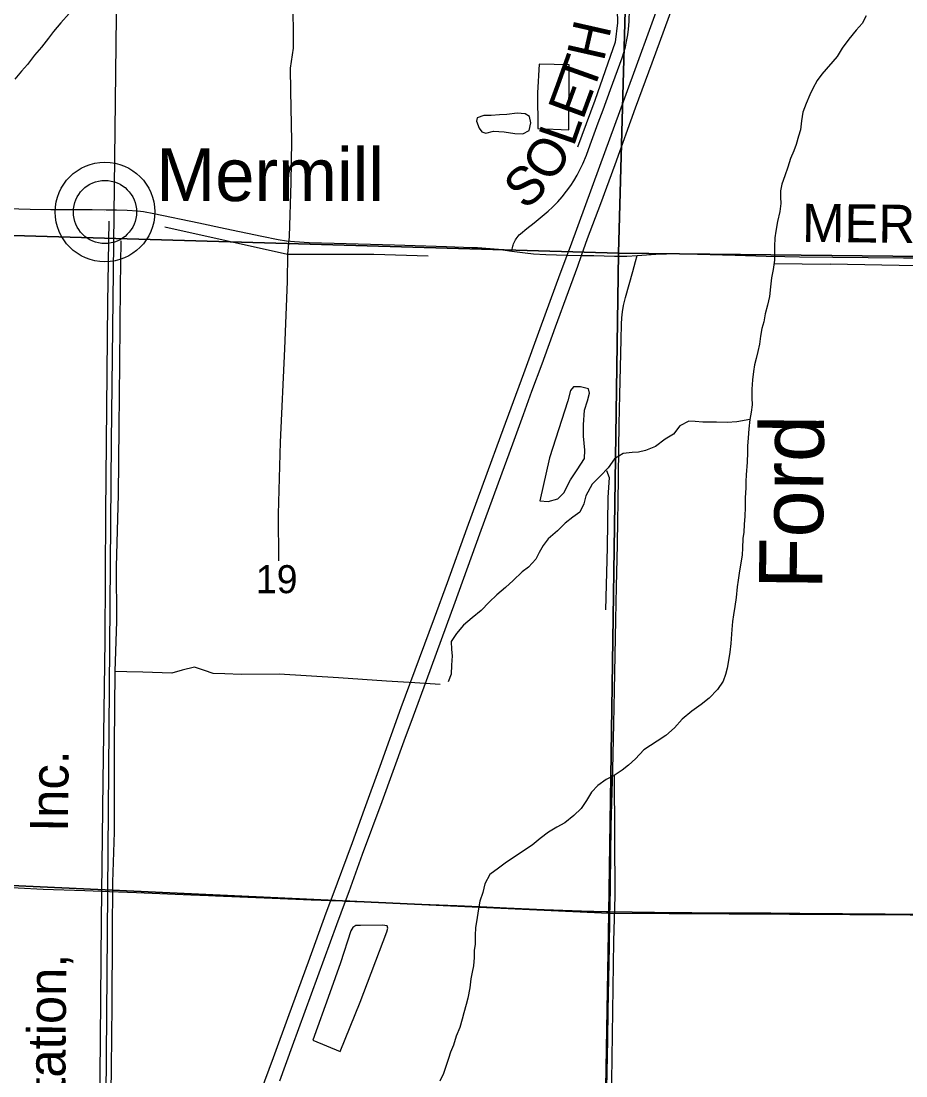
# Model space of a CAD drawing. Extents: x 1443599 to 1910620, y 1028088 to 1361369.
# Drawn here: x 1652830 to 1659809, y 1196448 to 1204767 of the extents above; entities that cross this region are included whole.
import ezdxf

# ---------------------------------------------------------------- set-up
doc = ezdxf.new("R2010")
doc.units = 0
for name, color, linetype in [('GM_X_County_Road', 7, 'Continuous'), ('GM_X_County_Road_Text', 7, 'Continuous'), ('GM_X_Interstate_Route', 7, 'Continuous'), ('GM_X_Major_River', 7, 'Continuous'), ('GM_X_Minor_Lake', 7, 'Continuous'), ('GM_X_Minor_River', 7, 'Continuous'), ('GM_X_Minor_River_Text', 7, 'Continuous'), ('GM_X_Rail_Line', 7, 'Continuous'), ('GM_X_Rail_Line_Text', 7, 'Continuous'), ('GM_X_Section', 7, 'Continuous'), ('GM_X_Section_Text', 7, 'Continuous'), ('GM_X_State_Route', 7, 'Continuous'), ('GM_X_Township_Road', 7, 'Continuous'), ('GM_X_Township_Road_Text', 7, 'Continuous'), ('GM_X_Unincorporated', 7, 'Continuous'), ('GM_X_Unincorporated_Location', 7, 'Continuous'), ('GM_X_Unincorporated_Text', 7, 'Continuous')]:
    doc.layers.add(name, color=color, linetype=linetype)

msp = doc.modelspace()

# ---------------------------------------------------------------- linework, layer by layer
at = {"layer": 'GM_X_County_Road'}
for points in [[(1652723.3, 1203288.1), (1652902, 1203285.3), (1653063.3, 1203281.9), (1653225.3, 1203281.7), (1653356.5, 1203281.9), (1653389.3, 1203281.1), (1653501.9, 1203279.5), (1653518.4, 1203279.8), (1653583.4, 1203278.8), (1653665.5, 1203276), (1653747.6, 1203270.4), (1653796.7, 1203264.5), (1653877.8, 1203250.5), (1654231.4, 1203176.9), (1654440.1, 1203132.7), (1654729.3, 1203072.1), (1654857.7, 1203045.3), (1654922.3, 1203034.8), (1654987.3, 1203028.2), (1655101.8, 1203022), (1655298.6, 1203017), (1655774.5, 1203003.8), (1656184.6, 1202990.6), (1656385.4, 1202982.4)], [(1656385.4, 1202982.4), (1656430.7, 1202980.5), (1656529.2, 1202974.1), (1656594.6, 1202967.2), (1656700.6, 1202952.9)], [(1656700.6, 1202952.9), (1656805.8, 1202938.7), (1656870.9, 1202932.6), (1656969, 1202927.5), (1657138.1, 1202922.4), (1657251.5, 1202919.7), (1657346.3, 1202917.5), (1657510.3, 1202913.7), (1657608.5, 1202914.1), (1657689.5, 1202917.9)], [(1657689.5, 1202917.9), (1657690.2, 1202918), (1657837.4, 1202928.9), (1657919.6, 1202932.4), (1658018.2, 1202933.2), (1658148.9, 1202930.5)], [(1658148.9, 1202930.5), (1658166, 1202930.1), (1658461.2, 1202920.3), (1658707.3, 1202913.5), (1658855, 1202910.7), (1658969.8, 1202908.8), (1659232.4, 1202905.8), (1659511.4, 1202903.2), (1659790.3, 1202899.4), (1660003.8, 1202898.9), (1660463.3, 1202894.1), (1660726, 1202891.3), (1660873.6, 1202889.6), (1661201.9, 1202888.9), (1661382.5, 1202888.2), (1661809.2, 1202883.8), (1662104.6, 1202881.3), (1662744.8, 1202877.5), (1662843, 1202876.5)]]:
    msp.add_lwpolyline(points, dxfattribs=at)
at = {"layer": 'GM_X_Interstate_Route'}
for points in [[(1654870, 1196408.2), (1654971.3, 1196685.7), (1655321.2, 1197641.2), (1655389.1, 1197827.1), (1655416.9, 1197903.3), (1655522.8, 1198196.6), (1655677.9, 1198611.7), (1655852.6, 1199089.6), (1655924.9, 1199288.3), (1656026.6, 1199567.6), (1656185.2, 1199999), (1656252.6, 1200184), (1656449.2, 1200723.7), (1656594.7, 1201124.9), (1656708.1, 1201432.9), (1656791.6, 1201664.5), (1656859.5, 1201849.4), (1656939.9, 1202064.7), (1657046.2, 1202356.3), (1657147.9, 1202635.2), (1657221.4, 1202835.5), (1657251.5, 1202919.7), (1657298.7, 1203051.8), (1657401.6, 1203328.8), (1657514.7, 1203636.9), (1657677.1, 1204084.3), (1657806.9, 1204438.7), (1658127.8, 1205317.5)], [(1654718.1, 1196316.8), (1654820, 1196594.1), (1654944.2, 1196933.2), (1655097.4, 1197349), (1655236.4, 1197735.1), (1655272.8, 1197831.8), (1655282.6, 1197857.9), (1655442.9, 1198288.7), (1655537.4, 1198551.2), (1655662.6, 1198889.9), (1655828.8, 1199353.4), (1655897, 1199538.1), (1656091.7, 1200061.2), (1656192.1, 1200339.1), (1656349.5, 1200770.8), (1656506.6, 1201202.7), (1656614.6, 1201495.3), (1656794.6, 1201988.7), (1656925, 1202343), (1657082.5, 1202774.7), (1657111.1, 1202851.5), (1657138.1, 1202922.4), (1657163.5, 1202989.6), (1657394, 1203621.9), (1657590.7, 1204161.6), (1657888.7, 1204978.9)]]:
    msp.add_lwpolyline(points, dxfattribs=at)
at = {"layer": 'GM_X_Major_River'}
for points in [[(1653208.1, 1204826.6), (1653143.8, 1204754.6), (1653085.5, 1204684.5), (1653045.3, 1204632.5), (1652990.9, 1204560.5), (1652936.7, 1204498.5), (1652880.3, 1204424.4)], [(1652880.3, 1204424.4), (1652832.1, 1204372.4), (1652781.8, 1204310.4)]]:
    msp.add_lwpolyline(points, dxfattribs=at)
at = {"layer": 'GM_X_Minor_Lake'}
for p, q in [((1656915, 1204426.7), (1656904.2, 1204202.1)), ((1656661.3, 1204030.3), (1656603.2, 1204028.5)), ((1656997.5, 1201321.6), (1656920.4, 1200984.9)), ((1655348.8, 1197338.8), (1655265.9, 1197104.3))]:
    msp.add_line(p, q, dxfattribs=at)
for points in [[(1656904.2, 1204202.1), (1656905.4, 1203919.3), (1657149.7, 1203910.6), (1657153.3, 1204422), (1656915, 1204426.7)], [(1656603.2, 1204028.5), (1656537.1, 1204022.7), (1656481, 1204022.8), (1656426.8, 1204004.9), (1656420.7, 1203976.9), (1656442.6, 1203922.7), (1656464.6, 1203894.5), (1656494.6, 1203884.4), (1656556.7, 1203898.3), (1656640.8, 1203894), (1656724.9, 1203881.8), (1656787, 1203877.6), (1656837.2, 1203903.5), (1656851.4, 1203965.6), (1656839.5, 1204013.8), (1656805.6, 1204035.9), (1656743.5, 1204042.1), (1656661.3, 1204030.3)], [(1656920.4, 1200984.9), (1656988.5, 1200978.7), (1657064.7, 1201000.5), (1657110.9, 1201046.5), (1657163.3, 1201148.7), (1657215.6, 1201228.8), (1657274, 1201316.8), (1657276.2, 1201383), (1657266.5, 1201493.4), (1657264.8, 1201583.6), (1657275.1, 1201699.9), (1657297.4, 1201772.1), (1657313.6, 1201832.2), (1657305.7, 1201866.3), (1657241.6, 1201882.6), (1657187.5, 1201882.7), (1657163.4, 1201852.7), (1657141.1, 1201772.5), (1656997.5, 1201321.6)], [(1655265.9, 1197104.3), (1655130.6, 1196729.6), (1655346.7, 1196640.8), (1655504.1, 1197029.4), (1655714.1, 1197584.5), (1655722.2, 1197614.5), (1655718.2, 1197630.6), (1655680.2, 1197636.7), (1655507.9, 1197635.2), (1655469.9, 1197635.3), (1655447.8, 1197619.3), (1655431.7, 1197593.3), (1655348.8, 1197338.8)]]:
    msp.add_lwpolyline(points, dxfattribs=at)
at = {"layer": 'GM_X_Minor_River'}
for points in [[(1655072, 1208204.2), (1656079.6, 1208169.2), (1657153.2, 1208123.9), (1657650, 1208106.4), (1657618.1, 1207553.1), (1657619.4, 1207342.5), (1657606.7, 1207138), (1657597.8, 1206853.3), (1657593.3, 1206694.9), (1657584.1, 1206317.9), (1657560.2, 1205748.5), (1657562.8, 1205299.2), (1657553.8, 1205000.4), (1657529.7, 1204962.4), (1657535, 1204753.8), (1657516.5, 1204601.4), (1657435.7, 1204375.1), (1657354.8, 1204140.6), (1657288.1, 1203958.3), (1657219.4, 1203772)], [(1654978, 1205694.1), (1654970.7, 1205350.9), (1654973.5, 1204971.9), (1654976.2, 1204554.7), (1654951.6, 1204396.3), (1654955.1, 1204213.8), (1654963.9, 1203822.7), (1654958.8, 1203493.8), (1654945.5, 1203068.6), (1654931, 1202928.2), (1654928.4, 1202713.6), (1654906.7, 1202182.2), (1654872.4, 1201446.2), (1654856.6, 1200878.6), (1654861.5, 1200509.5)], [(1659494.4, 1204810.1), (1659463.2, 1204748.5), (1659416.1, 1204695.2), (1659358.6, 1204624.1), (1659307.1, 1204554.9), (1659265.8, 1204487.4)], [(1659265.8, 1204487.4), (1659146.4, 1204350), (1659110.2, 1204298), (1659073.9, 1204235.9), (1659051.7, 1204185.8), (1659021.5, 1204117.7), (1658997.2, 1204049.6), (1658985, 1203979.4), (1658976.7, 1203909.3), (1658962.6, 1203859.2), (1658944.3, 1203795.1), (1658924.1, 1203743), (1658899.9, 1203682.9), (1658877.7, 1203614.7), (1658853.4, 1203546.6), (1658831.2, 1203480.5), (1658819, 1203428.4), (1658818.8, 1203378.2), (1658822.7, 1203328.1), (1658814.5, 1203265.9), (1658796.2, 1203185.8), (1658784, 1203111.6), (1658775.8, 1203057.5), (1658771.6, 1202989.3), (1658771.2, 1202883), (1658763, 1202808.8), (1658748.8, 1202742.6), (1658740.5, 1202670.5), (1658734.3, 1202596.3), (1658716, 1202528.1), (1658697.8, 1202458), (1658687.6, 1202395.8), (1658671.4, 1202343.7), (1658663.2, 1202283.6), (1658653, 1202219.4), (1658640.8, 1202161.3), (1658626.6, 1202107.2), (1658614.4, 1202057.1), (1658606.3, 1202004.9), (1658600, 1201936.8), (1658593.8, 1201864.6), (1658593.6, 1201796.4), (1658595.4, 1201740.2), (1658587.2, 1201684.1), (1658579, 1201623.9), (1658570.8, 1201551.8), (1658564.6, 1201479.6), (1658560.4, 1201415.4), (1658560.2, 1201365.2), (1658556, 1201289), (1658547.7, 1201188.8), (1658545.5, 1201136.6), (1658545.3, 1201086.5), (1658541.1, 1201008.3), (1658540.9, 1200932.1), (1658538.7, 1200861.8), (1658534.5, 1200797.7), (1658530.3, 1200735.5), (1658522.1, 1200685.4), (1658519.8, 1200609.2), (1658517.7, 1200559), (1658509.5, 1200506.9), (1658495.3, 1200432.7), (1658485, 1200358.5), (1658478.9, 1200306.4), (1658470.6, 1200220.2), (1658458.4, 1200150), (1658450.1, 1200083.8), (1658442, 1200031.7), (1658435.8, 1199967.6), (1658427.4, 1199859.2), (1658419.2, 1199791.1), (1658411, 1199740.9), (1658398.8, 1199664.8), (1658386.6, 1199614.7), (1658366.4, 1199560.6), (1658324.1, 1199494.5), (1658257.8, 1199428.5), (1658193.6, 1199376.5), (1658119.3, 1199324.6), (1658045, 1199260.6), (1657984.7, 1199192.6), (1657916.4, 1199132.6), (1657848.1, 1199088.7), (1657793.9, 1199054.7), (1657741.8, 1199018.8), (1657675.4, 1198948.8), (1657621.2, 1198898.8), (1657571, 1198858.8), (1657506.8, 1198816.9), (1657444.6, 1198787), (1657378.3, 1198739), (1657330.1, 1198685), (1657289.8, 1198618.9), (1657247.6, 1198556.9), (1657189.3, 1198500.9), (1657119, 1198444.9), (1657056.8, 1198409), (1656990.6, 1198369.1), (1656924.3, 1198321.1), (1656862.1, 1198269.1)], [(1653521.5, 1203189.1), (1653511.5, 1202545.3), (1653496.5, 1200892.6), (1653491.4, 1199881.6), (1653474, 1198772.4), (1653460.7, 1197675.2), (1653453.9, 1196738.5), (1653448.2, 1196178.9), (1653440.7, 1195035.5), (1653442.5, 1194299.4), (1653439.3, 1193894.2), (1653438.9, 1193077.8), (1653429.5, 1192616.5), (1653414.3, 1191555.4), (1653397.6, 1190680.9), (1653393, 1189816.3), (1653376, 1188827.5), (1653374.7, 1188382.2), (1653361.5, 1187985.1), (1653355.9, 1187437.5), (1653349.1, 1187192.8), (1653345.1, 1186524.8), (1653350.6, 1185955.6)], [(1653964.1, 1203143.7), (1654931, 1202928.2), (1655291.6, 1202929.2), (1655612.2, 1202928.3), (1656040.8, 1202917)], [(1653617.2, 1203034.4), (1653610.1, 1202677.4), (1653606.2, 1202065.6), (1653600.7, 1201562.2), (1653595, 1201030.7), (1653579.3, 1200465.1), (1653582, 1200033.8), (1653568.8, 1199636.7), (1653563, 1199061), (1653562.9, 1198371), (1653549.7, 1197975.9), (1653548.5, 1197560.7), (1653544.8, 1197005), (1653539.3, 1196511.6), (1653533.6, 1195935.9), (1653528, 1195402.4), (1653525.7, 1194662.2), (1653528.1, 1194118.6)], [(1658768.2, 1202855.7), (1659213.1, 1202850)], [(1667502.3, 1202759.8), (1666021.5, 1202770), (1664822.3, 1202787.9), (1663686.8, 1202778.5), (1662734.4, 1202797.9), (1662590.1, 1202802.5), (1662114.8, 1202809.2), (1661427.1, 1202823.7), (1660835.4, 1202826.5), (1659890.8, 1202837.7), (1659213.1, 1202850)], [(1658579, 1201623.9), (1658474.8, 1201606.2), (1658398.7, 1201602.4), (1658314.5, 1201604.6), (1658208.4, 1201605), (1658146.3, 1201609.1), (1658096.2, 1201611.3), (1658026, 1201575.4), (1657975.7, 1201509.4), (1657909.5, 1201469.4), (1657833.2, 1201411.5), (1657754.9, 1201379.6), (1657700.8, 1201367.7), (1657648.7, 1201365.9), (1657578.6, 1201358.1), (1657510.3, 1201314.1), (1657460, 1201244.1), (1657399.7, 1201180.1), (1657333.4, 1201116.1), (1657283.1, 1201022), (1657268.9, 1200959.8), (1657236.6, 1200893.7), (1657182.4, 1200855.8), (1657122.2, 1200807.8), (1657059.9, 1200747.8), (1656987.6, 1200683.8), (1656947.3, 1200631.8), (1656915.1, 1200575.7), (1656890.9, 1200523.6), (1656832.6, 1200461.6), (1656782.4, 1200423.7), (1656710.1, 1200355.7), (1656649.8, 1200299.7), (1656581.5, 1200241.7), (1656521.3, 1200183.7), (1656459, 1200119.7), (1656386.7, 1200061.8), (1656320.4, 1200003.8), (1656264.1, 1199937.8), (1656221.8, 1199873.7), (1656223.7, 1199811.5), (1656229.5, 1199761.3), (1656225.3, 1199687.1), (1656221.1, 1199616.9), (1656198.8, 1199554.8)], [(1657448, 1201222.1), (1657467.8, 1201167.8), (1657457.3, 1201009.4), (1657452.1, 1200616.3), (1657438.6, 1200124.9)], [(1656136.7, 1199534.9), (1655934.4, 1199547.6), (1655712.1, 1199560.2), (1655333.5, 1199587.4), (1654866.8, 1199616.9), (1654566.3, 1199613.7), (1654438.1, 1199618.1), (1654346, 1199622.4), (1654276, 1199646.7), (1654197.9, 1199673), (1654101.7, 1199647.2), (1654018.9, 1199623.3), (1653789.1, 1199632), (1653664.5, 1199636.2), (1653568.8, 1199636.7)], [(1657506.8, 1198816.9), (1657511.9, 1197866.1), (1657502.8, 1197511.1), (1657484.9, 1196221.3), (1657469.8, 1195208.4), (1657463.4, 1194410.1), (1657451.8, 1193856.5), (1657431.3, 1193062.2), (1657411.8, 1192556.8), (1657309.3, 1192450.8), (1657306.6, 1191558.1), (1657294.5, 1190870.2), (1657278.1, 1190065.8), (1657240.2, 1189442.1), (1657216.5, 1188894.6), (1657197.1, 1188449.3), (1657177.7, 1187982), (1657153.9, 1187380.3)], [(1656862.1, 1198269.1), (1656785.8, 1198217.2), (1656733.6, 1198183.3), (1656659.3, 1198133.3), (1656595.1, 1198087.4), (1656526.8, 1198035.4), (1656488.5, 1197963.3), (1656472.3, 1197895.2), (1656448, 1197827.1), (1656435.8, 1197748.8), (1656423.6, 1197678.7), (1656413.4, 1197618.5), (1656411.2, 1197556.3), (1656411, 1197488.2), (1656404.8, 1197438), (1656402.6, 1197381.9), (1656398.4, 1197315.7), (1656388.3, 1197265.6), (1656378.1, 1197213.4), (1656369.9, 1197143.3), (1656353.6, 1197061.1), (1656341.4, 1197011), (1656323.2, 1196944.8), (1656309, 1196894.7), (1656290.8, 1196830.6), (1656262.5, 1196762.5), (1656240.3, 1196690.3), (1656218.1, 1196634.2), (1656199.9, 1196584.1), (1656181.7, 1196530), (1656161.5, 1196465.9), (1656133.2, 1196405.8)]]:
    msp.add_lwpolyline(points, dxfattribs=at)
at = {"layer": 'GM_X_Rail_Line'}
msp.add_lwpolyline([(1653422.3, 1187382.1), (1653486.6, 1194668.7), (1653543.3, 1201447.8), (1653624.5, 1208390), (1653686.5, 1213883.3), (1653700.4, 1216254.3), (1653748.8, 1223261.5), (1653782.8, 1225132.4), (1653807.3, 1225844.8), (1653831.2, 1226150), (1653902.6, 1226760.6), (1654109.2, 1228858.3), (1654149, 1229281), (1654189.7, 1229712.5), (1654201, 1230000), (1654206.7, 1230284.6), (1654220.8, 1231414.3)], dxfattribs=at)
at = {"layer": 'GM_X_Section'}
for points in [[(1652280.2, 1208398.5), (1657685.6, 1208189.4), (1657542.6, 1202937.2), (1652222.6, 1203091.2), (1652221.2, 1203287.2)], [(1657685.6, 1208189.4), (1663011.9, 1208123.5), (1662830.5, 1202879.6), (1657542.6, 1202937.2)], [(1652222.6, 1203091.2), (1657542.6, 1202937.2), (1657466.1, 1197732.2), (1652183.4, 1197975.7)], [(1662830.5, 1202879.6), (1662691.8, 1197703.2), (1657466.1, 1197732.2), (1657542.6, 1202937.2)], [(1652183.4, 1197975.7), (1657466.1, 1197732.2), (1657375.8, 1192533.3), (1654528.8, 1192692.8), (1652172.1, 1192703.8)], [(1662691.8, 1197703.2), (1662664.5, 1192471.6), (1657375.8, 1192533.3), (1657466.1, 1197732.2)]]:
    msp.add_lwpolyline(points, close=True, dxfattribs=at)
at = {"layer": 'GM_X_State_Route'}
for points in [[(1652215.3, 1197977.8), (1652332.1, 1197969.1), (1652626.5, 1197944.5), (1652806.7, 1197932), (1653003.5, 1197922.1), (1653331.5, 1197910), (1653528.3, 1197902.3), (1653741.4, 1197893.5), (1654167.8, 1197876.4), (1654308.7, 1197870.6)], [(1654308.7, 1197870.6), (1654364.6, 1197868.3), (1654872.7, 1197847.7), (1655118.7, 1197837.8), (1655272.8, 1197831.8), (1655364.7, 1197828.1), (1655389.1, 1197827.1), (1655610.7, 1197818.1), (1655791, 1197811.4), (1655987.7, 1197802.8), (1656266.4, 1197790.9), (1656446.7, 1197783.4), (1656451, 1197783.2)], [(1656451, 1197783.2), (1656659.8, 1197773.7), (1656955, 1197760.9), (1657250.3, 1197750.7), (1657447.2, 1197744.3), (1657474.7, 1197744), (1657824.7, 1197740.1), (1658120.2, 1197737.5), (1658432, 1197734.8), (1658743.9, 1197734.3), (1658973.6, 1197732.1), (1659646.5, 1197726.6), (1660155.3, 1197723.2)]]:
    msp.add_lwpolyline(points, dxfattribs=at)
at = {"layer": 'GM_X_Township_Road'}
for points in [[(1656700.6, 1202952.9), (1656703.2, 1202969.8), (1656704.9, 1202980.3), (1656707.6, 1202991.3), (1656710.4, 1203000.6), (1656714.2, 1203011), (1656718, 1203019.8), (1656724.1, 1203031.9), (1656729.6, 1203041.2), (1656735.8, 1203050.5), (1656743.8, 1203061.5), (1656751.7, 1203071.4), (1656759.7, 1203080.7), (1656769.1, 1203090), (1656818.4, 1203131.8), (1656876.4, 1203177.5), (1656940.8, 1203228.4), (1656988.3, 1203268.9), (1657021.7, 1203300.4), (1657062.8, 1203342.9), (1657097.5, 1203382.3), (1657132.4, 1203425.8), (1657165.5, 1203470.8), (1657188.9, 1203506.5), (1657215.6, 1203551.8), (1657243.2, 1203604), (1657261.4, 1203642.5), (1657288.6, 1203709.5), (1657319.8, 1203792.5), (1657382.4, 1203965.3), (1657419.8, 1204067), (1657479.1, 1204227.2), (1657569.7, 1204477.2), (1657586.2, 1204527.1), (1657596.9, 1204565), (1657606.3, 1204606.6), (1657615.5, 1204658.4), (1657621.1, 1204704), (1657625.2, 1204762.9), (1657629.1, 1204858.1)], [(1657562, 1202256.9), (1657564.5, 1202376.9), (1657567.8, 1202426), (1657573.7, 1202474.9), (1657582.6, 1202523.3), (1657598.5, 1202587), (1657656.4, 1202792.3), (1657677.3, 1202871.6), (1657689.5, 1202917.9)], [(1657474.7, 1197744), (1657475, 1197765), (1657479.2, 1197961.9), (1657485.2, 1198421.5), (1657496.5, 1198864.6), (1657504.5, 1199225.7), (1657510.2, 1199488.3), (1657515.9, 1199767.3), (1657522.1, 1200046.3), (1657526.1, 1200308.9), (1657533, 1200637.2), (1657537, 1200834.1), (1657540.3, 1200965.4), (1657545.5, 1201392.2), (1657546.6, 1201589.1), (1657552.7, 1201818.9), (1657562, 1202256.9)], [(1657388.8, 1192546.6), (1657388.7, 1192562.1), (1657388.8, 1192660.6), (1657396.4, 1193038.1), (1657404.2, 1193415.6), (1657420.1, 1193907.8), (1657424, 1194055.5), (1657429.5, 1194433), (1657430.4, 1194695.7), (1657433.3, 1195056.8), (1657437.8, 1195319.4), (1657441.7, 1195713.4), (1657443.8, 1196074.5), (1657450.4, 1196353.5), (1657457.1, 1196731), (1657460.5, 1196960.8), (1657471.1, 1197469.6), (1657473.7, 1197683), (1657474.7, 1197744)]]:
    msp.add_lwpolyline(points, dxfattribs=at)
at = {"layer": 'GM_X_Unincorporated'}
for radius in [392.8, 249]:
    msp.add_circle((1653491.5, 1203261.7), radius, dxfattribs=at)
at = {"layer": 'GM_X_Unincorporated_Location'}
msp.add_line((1653491.5, 1203261.7), (1653491.5, 1203261.7), dxfattribs=at)

# ---------------------------------------------------------------- texts
at = {"layer": 'GM_X_County_Road_Text'}
msp.add_text('MERMILL', height=300, rotation=359.40488, dxfattribs=at).set_placement((1658988.8, 1203026.7))
at = {"layer": 'GM_X_Minor_River_Text'}
msp.add_text('Ford', height=500.3, rotation=89.39224, dxfattribs=at).set_placement((1659149.6, 1200283.4))
at = {"layer": 'GM_X_Rail_Line_Text'}
for s, rotation, p in [('Inc.', 89.32632, (1653198.2, 1198371.1)), ('Transportation,', 89.50317, (1653164, 1194722.6))]:
    msp.add_text(s, height=299, rotation=rotation, dxfattribs=at).set_placement(p)
at = {"layer": 'GM_X_Section_Text'}
msp.add_text('19', height=221, rotation=0.00001, dxfattribs=at).set_placement((1654681.8, 1200255.3))
at = {"layer": 'GM_X_Township_Road_Text'}
for s, rotation, p in [('H', 77.228, (1657425.9, 1204442.7)), ('T', 70.37875, (1657339.7, 1204193.8)), ('E', 69.78402, (1657261, 1203980)), ('L', 70.85264, (1657187.9, 1203769.4)), ('O', 58.88868, (1657022.5, 1203481.6)), ('S', 40.96824, (1656803.9, 1203270.8))]:
    msp.add_text(s, height=300, rotation=rotation, dxfattribs=at).set_placement(p)
at = {"layer": 'GM_X_Unincorporated_Text'}
msp.add_text('Mermill', height=417, rotation=0.00001, dxfattribs=at).set_placement((1653896.4, 1203347.9))

doc.saveas('drawing.dxf')
